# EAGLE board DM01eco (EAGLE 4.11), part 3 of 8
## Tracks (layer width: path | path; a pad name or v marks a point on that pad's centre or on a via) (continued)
CYC_SEL4  (via drill 0.61) (continued)
  Top 0.152: v159.38,17.78 v146.69,5.08
  Route2 0.152: v116.84,3.81 128.27,3.81 128.91,4.45 146.05,4.45 v146.69,5.08 | v159.38,17.78 175.26,33.66 181.61,33.66 187.96,40.01 194.31,40.01 200.66,46.35 207.01,46.35 215.9,55.24 215.9,56.52 v219.07,59.69 | v215.9,67.31 215.9,67.95 241.3,93.34 241.3,94.62 241.94,95.25 241.94,97.16 242.57,97.79 C13.R2
  Route15 0.152: v116.84,3.81 113.67,6.99 107.95,6.99 104.14,10.79 97.79,10.79 91.44,17.14 86.36,17.14 69.85,33.66 63.5,33.66 60.33,36.83 53.98,36.83 40.01,50.8 34.29,45.09 30.48,45.09 D30.K2
  Bottom 0.152: v219.07,59.69 219.07,62.87 215.9,66.04 v215.9,67.31
CYC_SEL5  (via drill 0.61)
  Top 0.152: v121.92,278.13 105.41,278.13 81.92,254.64 81.92,252.09 81.28,251.46 A26.K2
  Route2 0.152: v230.5,114.94 231.14,114.94 233.04,116.84 233.04,118.11 234.95,120.02 234.95,123.19 230.5,127.64 231.78,128.91 231.78,134.62 v234.31,137.16 | v214,165.1 210.82,168.28 213.36,170.81 213.36,172.09 211.46,173.99 212.09,174.62 212.09,175.9 219.07,182.88 v219.07,193.68
  Route15 0.152: v219.07,193.68 219.07,198.12 209.55,207.65 208.28,207.65 196.85,219.08 191.77,219.08 167,243.84 166.37,243.84 165.1,245.11 165.1,246.38 149.22,262.25 142.24,262.25 126.36,278.13 v121.92,278.13
  Bottom 0.152: v230.5,114.94 233.68,111.76 233.68,109.86 235.59,107.95 234.31,106.68 234.31,104.14 238.76,99.7 238.76,99.06 241.94,95.89 241.94,94.62 242.57,93.98 242.57,92.71 C13.T2 | v234.31,137.16 236.22,139.06 235.59,139.7 235.59,143.51 v214,165.1
CYC_SEL6  (via drill 0.61)
  Top 0.152: v130.81,75.57 132.72,75.57 141.6,84.46 142.24,84.46 144.15,86.36 v144.15,87 | v167,69.22 v177.8,80.01 | v188.59,71.75 195.58,71.75 200.03,76.2 200.03,78.11 211.46,89.54 212.09,89.54 213.36,90.81 v219.07,90.81 | v234.31,76.84 242.57,85.09 C13.V2
  Route2 0.152: v14.61,215.9 15.88,217.17 15.88,245.11 17.14,246.38 17.14,250.19 A31.K2
  Route15 0.152: v14.61,215.9 14.61,205.11 15.88,203.84 15.88,192.41 57.78,150.5 60.96,150.5 88.27,123.19 v88.9,123.19 | v99.69,111.12 97.16,108.59 98.42,107.32 98.42,106.68 111.76,93.34 116.84,93.34 117.47,92.71 117.47,90.17 116.2,88.9 120.02,85.09 120.02,84.46 127.64,76.84 129.54,76.84 v130.81,75.57
  Bottom 0.152: v88.9,123.19 88.9,121.92 v99.69,111.12 | v144.15,87 144.15,86.36 154.31,76.2 155.57,76.2 158.75,73.03 163.19,73.03 v167,69.22 | v177.8,80.01 180.34,80.01 v188.59,71.75 | v219.07,90.81 219.07,88.27 222.25,85.09 222.25,84.46 224.79,81.92 229.24,81.92 v234.31,76.84
DA0  (via drill 0.61)
  Top 0.152: v322.58,201.93 321.94,201.93 319.4,199.39 319.4,197.49 B07.D2 | v317.5,213.36 317.5,217.17 v341.63,241.3
  Bottom 0.152: v322.58,201.93 322.58,204.47 324.49,206.38 v317.5,213.36 | v341.63,241.3 320.68,262.25 320.68,264.8 319.4,266.06 A07.D2
DA0-0  (via drill 0.61)
  Top 0.152: v347.35,87 343.54,87 342.9,86.36 342.9,85.73 334.64,77.47 333.38,77.47 320.04,64.14 320.04,62.87 319.4,62.23 319.4,60.96 D07.D2 | v354.33,83.82 358.14,83.82 394.33,120.02 394.33,122.56 394.97,123.19 C01.F2
  Bottom 0.152: v347.35,87 347.35,86.36 349.88,83.82 v354.33,83.82
DA0-1  (via drill 0.61)
  Top 0.152: v303.53,40.01 308.61,40.01 314.96,46.35 320.04,46.35 323.85,50.16 325.12,50.16 327.66,52.7 333.38,52.7 353.06,72.39 353.06,73.66 361.95,82.55 363.22,82.55 394.33,113.67 394.33,116.21 394.97,116.84 C01.J2
  Route15 0.152: v303.53,40.01 303.53,40.64 300.99,43.18 295.91,43.18 294,45.09 288.29,39.37 286.38,39.37 285.75,40.01 280.04,40.01 278.13,41.91 277.5,41.91 276.23,43.18 269.88,43.18 255.91,57.15 255.91,59.69 D12.D2
DA0-2  (via drill 0.61)
  Top 0.152: v247.01,15.88 v237.49,6.35 | v270.51,1.27 353.06,1.27 374.65,22.86 374.65,23.5 v393.7,42.55 | v377.19,73.03 377.19,74.3 v385.44,82.55
  Route2 0.152: v192.41,55.88 192.41,59.69 D17.D2 | v385.44,82.55 389.25,82.55 393.7,87 393.7,88.27 396.88,91.44 396.88,96.52 403.23,102.87 403.23,104.14 403.86,104.78 403.86,105.41 401.95,107.32 v401.32,106.68
  Route15 0.152: v393.7,42.55 395.61,44.45 389.89,50.16 389.89,51.43 392.43,53.98 377.19,69.22 v377.19,73.03
  Bottom 0.152: v192.41,55.88 193.04,55.88 203.84,45.09 203.84,43.18 202.56,41.91 203.2,41.27 203.2,40.01 207.65,35.56 207.65,34.92 211.46,31.12 212.09,31.12 236.85,6.35 v237.49,6.35 | v247.01,15.88 247.01,15.24 248.28,13.97 253.37,13.97 261.62,5.71 266.06,5.71 v270.51,1.27 | v401.32,106.68 401.32,107.32 399.42,109.22 396.88,109.22 395.61,110.49 C01.L2
DA0-3  (via drill 0.61)
  Top 0.152: v163.19,52.7 163.19,53.98 168.28,59.05 168.28,64.14 168.91,64.77 173.99,64.77 182.88,73.66 v183.51,73.66 | v201.29,73.03 214,73.03 215.9,74.93 217.17,74.93 v225.43,83.19
  Route2 0.152: v146.69,71.12 144.78,73.03 141.6,73.03 140.34,71.75 137.16,71.75 128.91,63.5 128.91,60.96 D22.D2 | v331.47,6.99 332.74,6.99 378.46,52.7 384.18,52.7 400.05,68.58 400.05,73.03 403.23,76.2 403.23,78.74 v403.86,79.38
  Route15 0.152: v183.51,73.66 183.51,74.3 187.96,78.74 193.68,73.03 v201.29,73.03 | v225.43,83.19 229.24,83.19 276.23,36.2 285.75,36.2 294,44.45 v331.47,6.99 | v403.86,79.38 403.86,83.82 405.13,85.09 400.05,90.17 400.05,91.44 399.42,92.08 399.42,93.98 401.32,95.89 396.88,100.33 396.88,102.87 395.61,104.14 C01.N2
  Bottom 0.152: v146.69,71.12 146.69,70.48 162.56,54.61 162.56,53.34 v163.19,52.7
DA0-4  (via drill 0.61)
  Top 0.152: v92.71,35.56 93.98,35.56 120.65,62.23 121.28,62.23 v123.19,64.14 | v157.48,40.01 159.38,38.1 160.66,39.37 161.29,39.37 178.44,56.52 178.44,59.05 177.16,60.32 179.07,62.23 v179.71,62.23 | v201.93,41.27 202.56,41.27 203.84,42.55 209.55,42.55 219.07,52.07 224.79,52.07 227.33,54.61 v227.33,55.24
  Route2 0.152: v335.28,12.07 337.19,12.07 381.63,56.52 381.63,59.05 380.37,60.32 381.63,61.59 386.08,61.59 387.35,62.87 387.35,65.41 386.08,66.67 393.06,73.66 393.7,73.66 394.97,74.93 387.99,81.92 386.08,81.92 385.44,81.28 383.54,83.19 384.81,84.46 384.81,85.73 389.25,90.17 389.89,90.17 394.33,94.62 394.33,97.16 394.97,97.79 C01.R2
  Bottom 0.152: v92.71,35.56 68.58,59.69 65.41,59.69 D27.D2 | v123.19,64.14 125.73,66.67 139.06,53.34 139.7,53.34 140.34,52.7 145.41,52.7 157.48,40.64 v157.48,40.01 | v179.71,62.23 182.88,59.05 184.15,59.05 v201.93,41.27 | v227.33,55.24 227.33,54.61 232.41,49.53 237.49,49.53 269.88,17.14 269.88,15.24 275.59,9.53 283.85,9.53 286.38,6.99 330.2,6.99 v335.28,12.07
DA0-5  (via drill 0.61)
  Top 0.152: v241.94,38.1 244.47,40.64 v244.47,44.45 | v216.53,76.84 v216.53,80.01 | v98.42,230.5 97.16,231.78 121.28,255.91 v121.92,255.91
  Route2 0.152: v401.95,68.58 400.69,68.58 384.18,52.07 384.18,46.35 v349.25,11.43
  Route15 0.152: v201.29,99.7 200.03,99.7 196.85,102.87 196.85,104.14 188.59,112.4 187.96,112.4 180.97,119.38 180.97,125.73 161.29,145.41 161.29,147.32 157.48,151.13 157.48,152.4 142.88,167 142.88,172.72 135.89,179.71 130.18,179.71 117.47,192.41 117.47,197.49 116.84,198.12 116.84,200.03 112.39,204.47 111.76,204.47 107.95,208.28 107.95,209.55 104.78,212.72 104.78,224.16 v98.42,230.5
  Bottom 0.152: v401.95,68.58 401.32,69.22 405.13,73.03 405.13,79.38 395.61,88.9 395.61,91.44 C01.T2 | v349.25,11.43 337.19,11.43 327.66,1.91 274.32,1.91 268.61,7.62 260.99,7.62 250.19,18.41 250.19,20.32 252.09,22.23 245.75,28.58 245.75,29.84 241.3,34.29 241.3,37.47 v241.94,38.1 | v244.47,44.45 244.47,48.89 v216.53,76.84 | v216.53,80.01 216.53,81.92 213.36,85.09 213.36,87 202.56,97.79 202.56,98.43 v201.29,99.7 | v121.92,255.91 121.92,257.81 117.47,262.25 117.47,264.8 116.2,266.06 A23.D2
DA0-6  (via drill 0.61)
  Top 0.152: v69.22,13.34 97.16,13.34 104.78,20.95 104.78,21.59 v108.58,25.4 | v159.38,1.91 159.38,5.08 180.34,26.04 180.97,26.04 v182.25,27.3 | v210.82,1.91 214.63,1.91 228.6,15.88 228.6,16.51 232.41,20.32 v234.95,20.32 | v250.19,5.08 265.43,5.08 267.97,7.62 269.24,7.62 v313.69,52.07
  Route2 0.152: v87.63,229.87 87.63,228.6 81.92,222.89 81.92,217.81 74.93,210.82 74.93,209.55 18.41,153.03 18.41,142.88 15.88,140.34 15.88,128.27 3.17,115.57 3.17,67.95 63.5,7.62 v69.22,13.34 | v360.68,17.14 361.31,17.14 396.88,52.7 396.88,58.42 403.23,64.77 403.23,66.04 403.86,66.67 403.86,67.95 401.32,70.48 403.23,72.39 403.23,75.57 403.86,76.2 403.86,78.11 405.13,79.38 396.88,87.63 395.61,86.36 C01.V2
  Route15 0.152: v87.63,229.87 86.36,229.87 66.67,249.56 66.67,255.27 55.88,266.06 52.7,266.06 A28.D2 | v108.58,25.4 109.86,25.4 117.47,17.78 123.19,17.78 132.08,8.89 152.4,8.89 v159.38,1.91 | v182.25,27.3 184.15,27.3 197.49,13.97 198.75,13.97 v210.82,1.91
  Bottom 0.152: v250.19,5.08 v234.95,20.32 | v313.69,52.07 313.69,50.16 346.07,17.78 352.43,17.78 353.06,17.14 v360.68,17.14
DA1  (via drill 0.61)
  Route2 0.152: v313.69,199.39 313.69,200.66 324.49,211.46 324.49,212.72 333.38,221.62 v333.38,225.43
  Route15 0.152: v333.38,225.43 333.38,229.87 323.85,239.4 323.85,240.66 320.68,243.84 320.68,261.62 321.94,262.89 A07.E2
  Bottom 0.152: v313.69,199.39 318.77,194.31 318.77,191.14 B07.F2
DA1-0  (via drill 0.61)
  Top 0.152: v318.77,62.87 318.77,63.5 340.36,85.09 340.36,85.73 341.63,87 342.26,87 353.06,97.79 353.06,98.43 354.33,99.7 354.96,99.7 362.58,107.32 363.22,107.32 378.46,122.56 381.63,122.56 382.27,123.19 C02.F2
  Bottom 0.152: v318.77,62.87 321.94,59.69 321.94,57.78 D07.E2
DA1-1  (via drill 0.61)
  Top 0.152: v285.75,80.65 285.12,80.65 262.25,57.78 259.08,57.78 D12.E2 | v325.75,62.23 325.75,63.5 330.2,67.95 332.11,67.95 333.38,69.22 333.38,70.48 346.07,83.19 351.15,83.19 365.76,97.79 365.76,98.43 367.03,99.7 367.67,99.7 381.63,113.67 381.63,116.21 382.27,116.84 C02.J2
  Bottom 0.152: v285.75,80.65 287.65,80.65 295.27,73.03 300.99,73.03 303.53,75.57 307.98,71.12 311.79,71.12 314.96,67.95 320.04,67.95 v325.75,62.23
DA1-2  (via drill 0.61)
  Top 0.152: v285.12,9.53 309.88,9.53 340.36,40.01 345.44,40.01 351.15,45.72 351.79,45.72 391.16,85.09 391.16,87 389.25,88.9 392.43,92.08 v393.06,92.08
  Route15 0.152: v285.12,9.53 280.67,13.97 260.99,13.97 257.81,17.14 251.46,17.14 249.56,19.05 248.28,19.05 247.01,20.32 247.01,20.95 231.78,36.2 226.06,36.2 219.71,42.55 213.36,42.55 199.39,56.52 195.58,56.52 D17.E2
  Bottom 0.152: v393.06,92.08 392.43,92.08 389.89,94.62 389.89,96.52 391.8,98.43 387.35,102.87 386.71,102.87 384.18,105.41 384.18,109.22 382.9,110.49 C02.L2
DA1-3  (via drill 0.61)
  Top 0.152: v154.31,77.47 153.67,77.47 147.96,71.75 147.96,70.48 135.25,57.78 132.08,57.78 D22.E2 | v184.15,63.5 186.06,63.5 193.68,71.12 197.49,71.12 v210.19,83.82 | v296.55,13.97 307.34,13.97 v318.13,24.77 | v364.49,73.03 365.12,73.03 368.3,76.2 368.3,78.74 370.84,81.28 370.84,83.19 v386.71,99.06
  Route2 0.152: v318.13,24.77 361.95,68.58 361.95,70.48 v364.49,73.03
  Route15 0.152: v154.31,77.47 158.75,73.03 170.18,73.03 177.8,65.41 182.25,65.41 182.88,64.77 183.51,64.77 184.15,64.14 v184.15,63.5
  Bottom 0.152: v210.19,83.82 211.46,83.82 219.07,76.2 219.07,74.93 251.46,42.55 256.54,42.55 257.18,41.91 257.18,37.47 260.35,34.29 260.35,33.66 276.86,17.14 283.21,17.14 286.38,13.97 v296.55,13.97 | v386.71,99.06 386.08,99.06 384.18,100.97 384.18,102.87 382.9,104.14 C02.N2
DA1-4  (via drill 0.61)
  Top 0.152: v108.58,90.17 107.95,89.54 107.95,88.27 102.87,83.19 92.08,83.19 85.09,76.2 85.09,74.93 81.28,71.12 79.38,71.12 68.58,60.32 68.58,57.78 D27.E2 | v134.62,64.77 136.53,64.77 142.88,71.12 145.41,71.12 146.69,72.39 147.96,72.39 154.31,78.74 154.31,80.65 v158.12,84.46 | v265.43,33.66 265.43,34.29 270.51,39.37 275.59,39.37 293.37,57.15 294.64,57.15 295.91,58.42 301.62,58.42 317.5,74.3 318.77,74.3 v321.94,77.47 | v335.28,65.41 337.82,62.87 340.36,65.41 345.44,65.41 352.43,72.39 352.43,74.93 v361.95,84.46 | v375.92,74.93 375.92,75.57 v388.62,88.27
  Route2 0.152: v169.54,74.93 177.8,74.93 187.96,85.09 189.23,85.09 191.13,87 v194.31,87
  Route15 0.152: v194.31,87 197.49,83.82 198.75,83.82 209.55,73.03 214.63,73.03 231.14,56.52 231.78,56.52 233.04,55.24 233.04,53.34 234.31,52.07 235.59,52.07 254,33.66 260.35,33.66 260.99,33.02 263.52,33.02 264.8,34.29 v265.43,33.66
  Bottom 0.152: v108.58,90.17 111.76,87 116.84,87 117.47,86.36 117.47,81.92 133.35,66.04 133.35,65.41 133.99,64.77 v134.62,64.77 | v158.12,84.46 158.75,84.46 159.38,83.82 160.66,83.82 v169.54,74.93 | v321.94,77.47 323.85,77.47 330.83,70.48 330.83,69.22 332.11,67.95 332.74,67.95 v335.28,65.41 | v361.95,84.46 362.58,83.82 368.3,83.82 368.94,83.19 369.57,83.19 370.84,81.92 370.84,80.01 v375.92,74.93 | v388.62,88.27 388.62,89.54 386.71,91.44 386.71,92.71 385.44,93.98 384.81,93.98 384.18,94.62 384.18,96.52 382.9,97.79 C02.R2
DA1-5  (via drill 0.61)
  Top 0.152: v381,48.26 379.73,46.99 378.46,46.99 351.79,20.32 346.71,20.32 331.47,5.08 305.44,5.08 304.8,4.45 290.83,4.45 v287.02,8.26
  Route2 0.152: v371.48,76.2 381,85.73 381,86.36 382.27,87.63 382.27,91.44 C02.T2 | v231.78,15.88 231.78,17.14 229.87,19.05 222.88,12.07 220.34,12.07 218.44,13.97 217.17,12.7 212.72,12.7 208.91,8.89 194.31,8.89 193.68,8.26 158.12,8.26 155.57,5.71 154.31,5.71 153.67,5.08 151.76,5.08 151.13,4.45 147.32,4.45 146.69,3.81 139.7,3.81 v139.06,3.18 | v5.08,123.19 1.27,127 13.34,139.06 13.34,148.59 66.67,201.93 66.67,211.46 69.85,214.63 69.85,217.17 114.3,261.62 117.47,261.62 118.75,262.89 A23.E2
  Route15 0.152: v371.48,76.2 371.48,74.3 387.35,58.42 387.35,54.61 v381,48.26 | v287.02,8.26 259.08,8.26 255.27,12.07 235.59,12.07 v231.78,15.88 | v104.14,30.48 97.79,36.83 91.44,36.83 v5.08,123.19
  Bottom 0.152: v139.06,3.18 132.72,3.18 121.92,13.97 121.28,13.97 107.31,27.94 106.68,27.94 v104.14,30.48
DA1-6  (via drill 0.61)
  Top 0.152: v130.18,285.75 125.73,281.3 99.69,281.3 97.79,279.4 85.09,279.4 83.82,278.13 73.66,278.13 67.31,271.78 60.96,271.78 55.88,266.7 55.88,264.16 A28.E2 | v244.47,187.33 243.84,187.33 241.3,184.78 241.3,181.61 242.57,180.34 v240.66,178.44 | v340.36,76.2 340.36,76.84 346.07,82.55 351.79,82.55 356.24,87 v360.05,87
  Route2 0.152: v360.05,87 360.05,85.09 362.58,82.55 365.12,82.55 370.84,76.84 370.2,76.2 371.48,74.93 382.27,85.73 C02.V2
  Route15 0.152: v130.18,285.75 132.72,288.29 136.53,288.29 149.22,275.59 149.22,274.95 152.4,271.78 158.12,271.78 200.03,229.87 205.74,229.87 211.46,224.16 212.72,224.16 213.36,223.52 218.44,223.52 232.41,209.55 233.04,209.55 234.95,207.65 234.95,203.84 233.68,202.56 241.94,194.31 241.94,191.77 240.66,190.5 243.84,187.33 v244.47,187.33 | v240.66,178.44 240.66,177.16 260.35,157.48 260.35,156.84 264.16,153.03 264.16,150.5 283.21,131.44 283.21,130.81 327.66,86.36 327.66,85.73 330.83,82.55 334.01,82.55 v340.36,76.2
DA2  (via drill 0.61)
  Top 0.152: v323.85,186.69 321.94,184.78 319.4,184.78 B07.J2 | v318.77,207.65 318.77,212.09 v341.63,234.95
  Route15 0.152: v323.85,186.69 323.85,187.96 318.77,193.04 322.58,196.85 324.49,194.94 327.02,194.94 328.93,196.85 318.77,207.01 v318.77,207.65
  Bottom 0.152: v341.63,234.95 323.21,253.37 323.21,255.91 322.58,256.54 A07.H2
DA2-0  (via drill 0.61)
  Top 0.152: v342.26,73.66 322.58,53.98 322.58,51.43 D07.H2 | v339.09,78.74 340.36,78.74 353.06,91.44 353.06,92.08 354.33,93.34 355.6,93.34 v375.92,113.67
  Bottom 0.152: v342.26,73.66 342.26,75.57 v339.09,78.74 | v375.92,113.67 375.92,114.3 370.84,119.38 370.84,122.56 370.2,123.19 C03.F2
DA2-1  (via drill 0.61)
  Top 0.152: v271.14,55.24 266.7,55.24 262.89,51.43 259.08,51.43 D12.H2
  Route2 0.152: v309.25,22.86 309.88,22.86 343.54,56.52 343.54,59.05 342.26,60.32 343.54,61.59 343.54,62.87 349.88,69.22 349.88,73.03 353.06,76.2 353.06,79.38 358.77,85.09 v358.77,88.27 | v355.6,98.43 355.6,99.7 359.41,103.51 359.41,104.14 368.94,113.67 368.94,116.21 369.57,116.84 C03.J2
  Bottom 0.152: v271.14,55.24 271.14,54.61 279.4,46.35 285.75,46.35 v309.25,22.86 | v358.77,88.27 358.77,93.34 355.6,96.52 v355.6,98.43
DA2-2  (via drill 0.61)
  Top 0.152: v259.08,20.95 260.99,19.05 262.25,20.32 262.89,20.32 284.48,41.91 284.48,42.55 285.75,43.81 287.02,43.81 295.27,52.07 298.45,52.07 302.89,47.62 307.34,52.07 307.98,52.07 314.96,59.05 320.04,59.05 320.68,59.69 320.68,64.14 321.31,64.77 326.39,64.77 330.83,69.22 330.83,73.66 v333.38,76.2
  Route2 0.152: v203.2,55.24 199.39,51.43 195.58,51.43 D17.H2 | v333.38,76.2 342.9,85.73 342.9,87 353.06,97.16 354.96,97.16 356.87,95.25 368.94,107.32 368.94,109.86 369.57,110.49 C03.L2
  Route15 0.152: v203.2,55.24 207.01,55.24 213.36,48.89 219.71,48.89 238.76,29.84 244.47,29.84 250.82,23.5 256.54,23.5 v259.08,20.95
DA2-3  (via drill 0.61)
  Top 0.152: v172.72,83.82 160.66,71.75 154.94,71.75 153.67,70.48 153.67,69.85 148.59,64.77 143.51,64.77 139.06,60.32 140.34,59.05 140.34,56.52 135.25,51.43 132.08,51.43 D22.H2 | v217.81,73.03 217.81,73.66 227.33,83.19 227.33,85.73 238.76,97.16 243.84,97.16 244.47,97.79 v244.47,98.43 | v373.38,109.86 375.29,107.95 374.01,106.68 371.48,106.68 370.2,105.41 C03.N2
  Route2 0.152: v190.5,66.04 192.41,64.14 193.04,64.77 200.03,64.77 203.2,67.95 209.55,67.95 213.36,71.75 216.53,71.75 v217.81,73.03 | v269.88,67.31 271.14,67.31 276.23,72.39 278.76,72.39 290.83,84.46 290.83,85.73 296.55,91.44 296.55,92.08 307.98,103.51 307.98,109.22 320.68,121.92 327.02,121.92 327.66,122.56 334.01,122.56 341.63,130.18 v342.26,130.18
  Route15 0.152: v244.47,98.43 245.11,98.43 247.65,95.89 247.65,93.34 243.21,88.9 264.16,67.95 269.24,67.95 v269.88,67.31
  Bottom 0.152: v172.72,83.82 172.72,83.19 189.87,66.04 v190.5,66.04 | v342.26,130.18 343.54,128.91 349.25,128.91 353.06,125.09 358.14,125.09 358.77,124.46 358.77,120.02 359.41,119.38 364.49,119.38 365.76,118.11 365.76,117.48 367.03,116.21 368.94,116.21 372.75,112.4 372.75,110.49 v373.38,109.86
DA2-4  (via drill 0.61)
  Top 0.152: v230.5,3.81 233.04,1.27 242.57,1.27 244.47,3.18 262.25,3.18 263.52,4.45 265.43,4.45 266.06,5.08 270.51,5.08 271.14,5.71 273.69,5.71 296.55,28.58 v296.55,29.21 | v357.5,88.27 357.5,88.9 365.76,97.16 368.94,97.16 369.57,97.79 C03.R2
  Route2 0.152: v142.88,2.54 144.15,2.54 144.78,3.18 156.21,3.18 156.84,3.81 161.93,3.81 163.19,5.08 177.8,5.08 179.71,6.99 188.59,6.99 189.23,7.62 214.63,7.62 v219.07,12.07 | v296.55,29.21 303.53,22.23 342.9,61.59 342.9,62.87 349.25,69.22 349.25,73.03 352.43,76.2 352.43,83.19 v357.5,88.27
  Route15 0.152: v142.88,2.54 140.34,5.08 132.08,5.08 130.81,6.35 125.73,6.35 125.09,6.99 120.65,6.99 113.67,13.97 108.58,13.97 93.34,29.21 92.08,29.21 90.81,30.48 90.81,31.12 71.75,50.16 68.58,50.16 D27.H2
  Bottom 0.152: v219.07,12.07 222.25,12.07 v230.5,3.81
DA2-5  (via drill 0.61)
  Top 0.152: v123.19,257.18 123.19,257.81 146.69,281.3 169.54,281.3 176.53,288.29 202.56,288.29 203.2,287.65 203.84,288.29 207.65,288.29 208.28,288.92 214,288.92 v215.9,290.83 | v375.92,96.52 375.92,95.89 372.11,92.08 370.2,92.08 C03.T2
  Route2 0.152: v215.9,290.83 215.9,290.19 217.17,288.92 248.92,288.92 250.82,290.83 260.99,290.83 262.25,289.56 v263.52,290.83 | v368.3,196.85 368.3,195.58 372.75,191.14 370.84,189.23 370.84,185.42 372.11,184.15 369.57,181.61 369.57,180.34 368.3,179.07 368.3,175.9 372.11,172.09 371.48,171.45 371.48,170.18 351.79,150.5 346.71,150.5 v342.9,146.69
  Route15 0.152: v123.19,257.18 119.38,257.18 A23.H2 | v329.56,255.27 325.12,250.83 333.38,242.57 333.38,236.22 368.94,200.66 368.94,198.75 367.67,197.49 v368.3,196.85 | v342.9,146.69 342.9,143.51 344.17,142.24 344.17,139.7 358.77,125.09 358.77,119.38 363.22,114.94 363.22,114.3 360.68,111.76 v361.31,111.12
  Bottom 0.152: v263.52,290.83 266.06,290.83 269.88,287.02 271.14,288.29 280.67,288.29 282.57,286.38 289.56,286.38 290.19,285.75 293.37,285.75 295.27,283.84 304.8,283.84 330.83,257.81 330.83,256.54 v329.56,255.27 | v361.31,111.12 361.31,110.49 362.58,109.22 364.49,109.22 366.39,111.12 371.48,106.05 371.48,100.33 375.29,96.52 v375.92,96.52
DA2-6  (via drill 0.61)
  Top 0.152: v237.49,217.81 237.49,214.63 228.6,205.74 228.6,205.11 219.07,195.58 217.81,195.58 v217.17,194.94
  Route2 0.152: v123.83,290.83 120.02,290.83 118.75,289.56 111.12,289.56 102.87,281.3 99.69,281.3 97.16,278.76 85.09,278.76 83.82,277.5 79.38,277.5 59.69,257.81 55.88,257.81 A28.H2 | v245.75,149.86 249.56,149.86 v250.82,151.13 | v285.75,127 287.65,127 294,120.65 302.26,128.91 310.51,128.91 311.79,127.64 v312.42,128.27
  Route15 0.152: v142.24,286.38 154.31,286.38 158.75,281.94 173.35,281.94 201.93,253.37 v201.93,252.73 | v219.07,235.59 224.16,230.5 224.79,230.5 v237.49,217.81 | v217.17,194.94 217.17,194.31 219.07,192.41 222.25,192.41 223.52,193.68 234.31,182.88 234.31,182.25 234.95,181.61 234.95,179.71 233.04,177.8 231.14,179.71 228.6,179.71 227.33,178.44 226.69,179.07 225.43,179.07 224.79,179.71 222.25,179.71 220.34,177.8 229.24,168.91 229.24,166.37 227.97,165.1 232.41,160.66 237.49,160.66 245.75,152.4 v245.75,149.86 | v312.42,128.27 312.42,127.64 314.96,125.09 321.31,125.09 340.36,106.05 348.62,106.05 350.52,107.95 354.96,103.51 356.24,103.51 v356.87,102.87
  Bottom 0.152: v123.83,290.83 137.79,290.83 v142.24,286.38 | v201.93,252.73 202.56,252.73 216.53,238.76 216.53,238.12 v219.07,235.59 | v250.82,151.13 254,151.13 254.63,150.5 257.18,150.5 271.14,136.53 271.14,135.89 272.42,134.62 275.59,134.62 277.5,136.53 281.94,132.08 281.94,131.44 285.75,127.64 v285.75,127 | v356.87,102.87 356.87,102.23 368.3,90.81 368.3,89.54 368.94,88.9 368.94,87 369.57,86.36 C03.V2
DA3  (via drill 0.61)
  Top 0.152: v313.69,238.12 313.69,239.4 320.68,246.38 320.68,248.92 321.94,250.19 A07.K2
  Route2 0.152: v325.12,173.36 325.12,173.99 339.73,188.59 339.73,189.23 349.25,198.75 v349.25,201.93
  Bottom 0.152: v325.12,173.36 325.12,173.99 321.94,177.16 319.4,177.16 B07.L2 | v349.25,201.93 348.62,201.93 318.77,231.78 318.77,232.41 313.69,237.49 v313.69,238.12
DA3-0  (via drill 0.61)
  Top 0.152: v313.06,62.23 313.06,64.14 340.36,91.44 340.36,92.08 341.63,93.34 342.26,93.34 361.95,113.03 v361.95,114.94
  Bottom 0.152: v313.06,62.23 313.69,62.23 320.68,55.24 320.68,50.16 321.94,48.89 321.94,45.09 D07.K2 | v361.95,114.94 361.95,116.21 358.14,120.02 358.14,122.56 357.5,123.19 C04.F2
DA3-1  (via drill 0.61)
  Top 0.152: v298.45,69.85 298.45,70.48 309.88,81.92 311.15,81.92 311.79,82.55 318.77,82.55 332.74,96.52 333.38,96.52 353.06,116.21 356.24,116.21 356.87,116.84 C04.J2
  Route2 0.152: v266.7,41.27 266.7,41.91 270.51,45.72 275.59,45.72 298.45,68.58 v298.45,69.85
  Bottom 0.152: v266.7,41.27 265.43,42.55 264.16,42.55 263.52,43.18 260.35,43.18 259.71,43.81 259.08,43.81 D12.K2
DA3-2  (via drill 0.61)
  Top 0.152: v247.65,1.27 253.37,1.27 254.63,2.54 262.25,2.54 263.52,3.81 265.43,3.81 266.06,4.45 270.51,4.45 271.14,5.08 273.69,5.08 v307.34,38.73 | v346.71,99.7 344.81,101.6 353.06,109.86 356.24,109.86 356.87,110.49 C04.L2
  Route2 0.152: v310.51,47.62 306.7,51.43 317.5,62.23 317.5,62.87 320.68,66.04 320.68,70.48 336.55,86.36 336.55,87 340.36,90.81 345.44,90.81 346.07,91.44 346.07,95.89 347.98,97.79 v348.62,97.79
  Route15 0.152: v218.44,30.48 217.17,31.75 217.17,33.02 215.9,34.29 215.26,34.29 207.01,42.55 200.66,42.55 199.39,43.81 195.58,43.81 D17.K2 | v348.62,97.79 v346.71,99.7
  Bottom 0.152: v247.65,1.27 v218.44,30.48 | v307.34,38.73 313.06,44.45 310.51,46.99 v310.51,47.62
DA3-3  (via drill 0.61)
  Top 0.152: v268.61,20.32 269.88,20.32 v299.08,49.53
  Route2 0.152: v154.94,70.48 154.31,70.48 148.59,64.77 142.88,64.77 128.91,50.8 131.44,48.26 131.44,45.09 D22.K2 | v193.68,31.12 193.68,32.38 196.85,35.56 196.85,36.2 200.66,40.01 208.28,40.01 211.46,36.83 212.09,36.83 214.63,34.29 216.53,36.2 221.62,36.2 236.85,51.43 v236.85,52.07 | v299.08,49.53 335.92,86.36 335.92,87 340.36,91.44 340.36,92.08 341.63,93.34 342.9,93.34 353.06,103.51 356.24,103.51 356.87,104.14 C04.N2
  Route15 0.152: v154.94,70.48 154.31,69.85 159.38,64.77 160.02,64.77 161.93,62.87 161.93,62.23 165.1,59.05 165.74,59.05 171.45,53.34 171.45,52.7 193.04,31.12 v193.68,31.12
  Bottom 0.152: v236.85,52.07 236.85,50.8 266.7,20.95 267.97,20.95 v268.61,20.32
DA3-4  (via drill 0.61)
  Top 0.152: v127,7.62 135.89,7.62 178.44,50.16 v178.44,50.8 | v351.15,72.39 351.15,74.93 352.43,76.2 352.43,77.47 365.76,90.81 v366.39,90.81
  Route2 0.152: v106.05,21.59 100.33,15.88 72.39,43.81 68.58,43.81 D27.K2 | v267.97,2.54 277.5,2.54 278.76,3.81 290.83,3.81 308.61,21.59 309.25,21.59 344.17,56.52 344.17,57.78 346.07,59.69 346.07,64.77 350.52,69.22 350.52,71.75 v351.15,72.39
  Route15 0.152: v178.44,50.8 179.07,50.8 193.68,36.2 193.68,34.92 195.58,33.02 196.22,33.02 196.85,32.38 196.85,29.84 195.58,28.58 210.19,13.97 212.72,13.97 218.44,8.26 220.34,8.26 223.52,5.08 225.43,5.08 229.24,1.27 242.57,1.27 247.65,6.35 252.73,6.35 254.63,4.45 266.06,4.45 v267.97,2.54 | v366.39,90.81 366.39,91.44 365.12,92.71 365.12,93.34 361.95,96.52 358.77,96.52 357.5,97.79 C04.R2
  Bottom 0.152: v106.05,21.59 107.31,21.59 111.76,17.14 117.47,17.14 v127,7.62
DA3-5  (via drill 0.61)
  Top 0.152: v203.84,232.41 204.47,232.41 209.55,237.49 v209.55,238.12
  Route2 0.152: v152.4,274.32 147.96,269.88 146.05,271.78 136.53,271.78 119.38,254.64 119.38,251.46 A23.K2 | v259.71,184.15 259.71,182.25 260.99,180.97 258.44,178.44 258.44,177.16 244.47,163.19 244.47,156.84 240.03,152.4 240.03,150.5 250.19,140.34 253.37,143.51 257.18,143.51 267.33,153.67 269.24,153.67 v269.88,153.03
  Route15 0.152: v152.4,274.32 156.21,274.32 190.5,240.03 196.22,240.03 v203.84,232.41 | v209.55,238.12 210.19,238.12 210.82,237.49 212.09,237.49 228.6,220.98 233.04,220.98 244.47,209.55 247.65,209.55 250.19,207.01 246.38,203.2 254,195.58 254,194.31 257.18,191.14 257.18,186.69 v259.71,184.15 | v277.5,150.5 281.31,150.5 284.48,147.32 285.75,147.32 301.62,131.44 302.89,131.44 305.44,128.91 310.51,128.91 320.68,118.75 320.68,118.11 323.21,115.57 324.49,115.57 327.66,112.4 333.38,112.4 345.44,100.33 345.44,99.7 348.62,96.52 349.25,97.16 353.06,93.34 356.24,93.34 356.87,92.71 C04.T2
  Bottom 0.152: v269.88,153.03 271.14,153.03 273.69,150.5 v277.5,150.5
DA3-6  (via drill 0.61)
  Top 0.152: v21.59,224.79 21.59,226.06 55.24,259.71 57.15,257.81 57.15,256.54 55.88,255.27 55.88,251.46 A28.K2 | v141.6,71.75 145.41,71.75 152.4,78.74 v153.03,78.74 | v312.42,10.79 335.92,10.79 382.27,57.15 382.27,57.78 v384.18,59.69
  Route15 0.152: v69.85,173.99 67.31,171.45 66.04,172.72 63.5,172.72 59.05,168.28 76.2,151.13 76.2,147.32 104.78,118.75 104.78,113.67 v107.31,111.12 | v153.03,78.74 152.4,78.11 162.56,67.95 168.91,67.95 188.59,48.26 189.23,48.26 196.85,40.64 196.85,40.01 200.66,36.2 206.38,36.2 225.43,17.14 232.41,17.14 236.85,12.7 264.8,12.7 266.7,10.79 v275.59,10.79
  Bottom 0.152: v21.59,224.79 21.59,224.16 38.73,207.01 38.73,206.38 46.35,198.75 46.99,198.75 69.85,175.9 v69.85,173.99 | v107.31,111.12 107.31,109.86 111.76,105.41 111.76,104.14 109.86,102.23 111.12,100.97 111.12,100.33 115.57,95.89 115.57,94.62 117.47,92.71 117.47,87.63 121.28,83.82 127.64,83.82 128.91,82.55 130.81,82.55 v141.6,71.75 | v275.59,10.79 v312.42,10.79 | v384.18,59.69 384.18,62.23 377.19,69.22 377.19,71.75 369.57,79.38 368.94,79.38 365.12,83.19 359.41,83.19 357.5,85.09 C04.V2
DA4  (via drill 0.61)
  Top 0.152: v321.94,170.18 319.4,167.64 318.13,168.91 318.77,169.55 318.77,170.81 B07.N2
  Route2 0.152: v321.94,170.18 323.21,170.18 325.12,168.28 328.3,171.45 329.56,171.45 332.74,174.62 332.74,175.9 346.07,189.23 346.07,194.94 v353.06,201.93
  Route15 0.152: v353.06,201.93 353.69,202.56 352.43,203.84 352.43,204.47 349.25,207.65 347.98,207.65 342.9,212.72 v342.9,220.34
  Bottom 0.152: v342.9,220.34 342.9,220.98 323.21,240.66 323.21,243.21 322.58,243.84 A07.M2
DA4-0  (via drill 0.61)
  Top 0.152: v336.55,51.43 336.55,49.53 325.75,38.73 322.58,38.73 D07.M2 | v332.11,69.22 332.11,69.85 353.06,90.81 v353.69,90.81 | v349.25,95.89 347.35,97.79 354.33,104.78 v354.96,104.78
  Route15 0.152: v336.55,51.43 336.55,53.34 333.38,56.52 333.38,67.95 v332.11,69.22 | v353.69,90.81 353.69,91.44 352.43,92.71 352.43,93.34 349.88,95.89 v349.25,95.89
  Bottom 0.152: v354.96,104.78 357.5,107.32 349.88,114.94 349.25,114.94 347.98,116.21 347.98,118.11 346.07,120.02 346.07,121.92 344.81,123.19 C05.F2
DA4-1  (via drill 0.61)
  Top 0.152: v287.65,64.77 279.4,56.52 279.4,55.24 262.89,38.73 259.08,38.73 D12.M2 | v321.31,81.28 323.85,81.28 327.66,85.09 327.66,85.73 328.93,87 329.56,87 349.25,106.68 v349.25,109.86
  Route2 0.152: v287.65,64.77 288.93,64.77 295.27,71.12 299.08,71.12 309.88,81.92 311.15,81.92 311.79,82.55 320.04,82.55 v321.31,81.28
  Bottom 0.152: v349.25,109.86 349.25,110.49 346.07,113.67 346.07,115.57 344.81,116.84 C05.J2
DA4-2  (via drill 0.61)
  Top 0.152: v214.63,55.24 214.63,54.61 202.56,42.55 201.93,42.55 200.66,41.27 200.66,40.64 198.75,38.73 195.58,38.73 D17.M2 | v328.3,97.16 333.38,97.16 343.54,107.32 343.54,109.86 344.17,110.49 C05.L2
  Route2 0.152: v245.75,27.3 245.75,28.58 260.99,43.81 261.62,43.81 286.38,68.58 287.02,68.58 288.93,70.48 288.93,71.12 289.56,71.75 291.46,71.75 v292.74,73.03 | v305.44,69.85 307.34,69.85 308.61,71.12 312.42,71.12 322.58,81.28 322.58,83.19 323.21,83.82 318.77,88.27 327.66,97.16 v328.3,97.16
  Bottom 0.152: v214.63,55.24 214.63,54.61 222.25,46.99 222.25,46.35 228.6,40.01 234.95,40.01 243.21,31.75 243.21,30.48 245.75,27.94 v245.75,27.3 | v292.74,73.03 294.64,73.03 295.27,72.39 303.53,72.39 305.44,70.48 v305.44,69.85
DA4-3  (via drill 0.61)
  Top 0.152: v280.67,56.52 289.56,65.41 291.46,65.41 v292.1,66.04 | v295.27,62.87 297.18,60.96 304.17,67.95 305.44,67.95 308.61,71.12 312.42,71.12 317.5,76.2 317.5,79.38 319.4,81.28 319.4,82.55 330.2,93.34 v334.64,93.34
  Route2 0.152: v147.32,20.32 148.59,20.32 155.57,27.3 156.84,27.3 v158.12,28.58 | v202.56,1.27 207.65,1.27 209.55,3.18 210.82,3.18 212.09,1.91 212.72,2.54 221.62,2.54 222.25,3.18 227.33,3.18 255.91,31.75 255.91,32.38 257.18,33.66 258.44,33.66 260.35,35.56 260.35,36.2 v280.67,56.52 | v334.64,93.34 335.28,93.34 336.55,94.62 336.55,95.89 334.64,97.79 340.36,103.51 343.54,103.51 344.17,104.14 C05.N2
  Bottom 0.152: v147.32,20.32 146.69,20.32 133.35,33.66 133.35,34.29 132.08,35.56 132.08,37.47 D22.M2 | v158.12,28.58 158.12,27.94 172.09,13.97 177.8,13.97 186.06,5.71 188.59,5.71 189.23,5.08 192.41,5.08 194.31,3.18 200.66,3.18 v202.56,1.27 | v292.1,66.04 v295.27,62.87
DA4-4  (via drill 0.61)
  Top 0.152: v66.67,28.58 66.67,32.38 69.22,34.92 68.58,35.56 68.58,37.47 D27.M2 | v200.66,1.27 201.29,1.27 202.56,2.54 205.74,2.54 v217.17,13.97 | v304.8,5.71 331.47,5.71 v383.54,57.78
  Route2 0.152: v66.67,28.58 66.67,26.67 62.87,22.86 62.87,21.59 72.39,12.07 84.45,12.07 95.25,1.27 109.22,1.27 114.3,6.35 116.84,6.35 127.64,17.14 132.72,17.14 146.05,30.48 148.59,30.48 151.13,27.94 153.67,30.48 v154.31,30.48
  Route15 0.152: v154.31,30.48 154.94,30.48 171.45,13.97 182.88,13.97 183.51,13.34 188.59,13.34 v200.66,1.27 | v217.17,13.97 220.34,13.97 222.25,12.07 224.16,12.07 228.6,7.62 239.4,7.62 240.03,6.99 266.7,6.99 268.61,5.08 304.17,5.08 v304.8,5.71
  Bottom 0.152: v383.54,57.78 382.27,57.78 368.3,71.75 363.22,71.75 358.77,76.2 358.77,80.65 349.25,90.17 349.25,91.44 346.07,94.62 346.07,96.52 344.81,97.79 C05.R2
DA4-5  (via drill 0.61)
  Top 0.152: v112.39,229.87 113.67,229.87 117.47,233.68 117.47,238.76 118.75,240.03 118.75,243.84 A23.M2
  Route2 0.152: v231.14,113.03 231.14,114.3 232.41,115.57 238.12,115.57 238.76,116.21 247.01,116.21 252.09,111.12 253.37,112.4 260.35,112.4 264.16,116.21 270.51,116.21 276.86,122.56 283.21,122.56 286.38,125.73 288.29,125.73 296.55,117.48 302.26,123.19 303.53,123.19 v306.7,126.37
  Route15 0.152: v112.39,229.87 112.39,229.24 133.99,207.65 134.62,207.65 136.53,205.74 136.53,205.11 139.06,202.56 139.7,202.56 146.05,196.22 146.05,195.58 147.32,194.31 147.32,193.04 v147.96,192.41 | v159.38,182.25 159.38,181.61 170.81,170.18 170.81,169.55 173.35,167 173.99,167 187.96,153.03 187.96,149.86 187.32,149.22 188.59,147.96 189.87,147.96 191.13,146.69 193.68,146.69 v194.94,147.96 | v306.7,126.37 320.68,112.4 320.68,111.76 324.49,107.95 325.75,107.95 327.66,106.05 333.38,106.05 343.54,95.89 343.54,93.34 344.17,92.71 C05.T2
  Bottom 0.152: v147.96,192.41 148.59,192.41 154.31,186.69 154.31,186.06 155.57,184.78 156.84,184.78 v159.38,182.25 | v194.94,147.96 197.49,147.96 204.47,140.97 204.47,140.34 210.19,134.62 212.09,134.62 214,136.53 219.07,131.44 219.07,125.09 v231.14,113.03
DA4-6  (via drill 0.61)
  Top 0.152: v87,208.91 78.11,200.03 77.47,200.03 73.03,195.58 73.03,194.31 v71.12,192.41 | v241.3,135.89 241.3,137.16 241.94,137.8 246.38,137.8 v259.08,150.5 | v335.92,76.84 344.17,85.09 C05.V2
  Route2 0.152: v123.19,141.61 136.53,141.61 138.43,143.51 153.67,143.51 155.57,145.41 161.29,145.41 162.56,146.69 163.83,146.69 165.74,144.78 173.99,144.78 v174.62,145.41 | v201.93,122.56 206.38,122.56 219.07,135.25 219.07,140.97 227.97,149.86 229.87,149.86 238.12,141.61 240.66,141.61 243.21,139.06 241.3,137.16 v241.3,135.89 | v316.23,103.51 316.87,103.51 322.58,97.79 v321.94,97.16
  Route15 0.152: v71.12,192.41 72.39,192.41 104.78,160.02 104.78,158.75 106.05,157.48 107.31,157.48 v123.19,141.61 | v174.62,145.41 175.9,145.41 178.44,142.88 178.44,140.97 187.96,131.44 193.68,131.44 201.93,123.19 v201.93,122.56 | v286.38,134.62 293.37,127.64 294,127.64 298.45,123.19 298.45,122.56 303.53,117.48 304.17,117.48 305.44,116.21 305.44,113.67 303.53,111.76 305.44,109.86 310.51,109.86 316.23,104.14 v316.23,103.51
  Bottom 0.152: v87,208.91 78.11,217.81 79.38,219.08 79.38,223.52 59.05,243.84 55.88,243.84 A28.M2 | v259.08,150.5 270.51,150.5 v286.38,134.62 | v321.94,97.16 320.04,95.25 320.04,93.34 320.68,92.71 320.68,87.63 324.49,83.82 328.93,83.82 v335.92,76.84
DA5  (via drill 0.61)
  Top 0.152: v295.27,208.28 296.55,209.55 298.45,209.55 301.62,212.72 301.62,214.63 v314.96,227.97
  Route2 0.152: v320.68,174.62 320.68,170.81 320.04,170.18 319.4,170.18 318.13,168.91 318.77,168.28 318.77,165.74 B07.R2 | v314.96,227.97 320.68,233.68 320.68,236.22 321.94,237.49 A07.P2
  Route15 0.152: v320.68,174.62 318.77,174.62 296.55,196.85 296.55,198.12 295.27,199.39 v295.27,208.28
DA5-0  (via drill 0.61)
  Top 0.152: v363.22,69.85 325.75,32.38 322.58,32.38 D07.P2 | v323.85,109.86 322.58,111.12 v331.47,120.02
  Bottom 0.152: v363.22,69.85 342.26,90.81 341.63,90.81 339.73,92.71 339.73,93.34 337.19,95.89 336.55,95.89 330.2,102.23 330.2,102.87 329.56,103.51 328.93,103.51 327.02,105.41 327.02,106.05 323.85,109.22 v323.85,109.86 | v331.47,120.02 331.47,123.19 C06.F2
DA5-1  (via drill 0.61)
  Top 0.152: v299.72,52.07 301.62,52.07 302.26,52.7 307.98,52.7 317.5,62.23 317.5,62.87 320.68,66.04 320.68,71.12 340.36,90.81 341.63,90.81 v342.9,92.08
  Route2 0.152: v299.72,52.07 299.08,51.43 297.81,52.7 288.93,52.7 272.42,36.2 266.7,36.2 262.89,32.38 259.08,32.38 D12.P2
  Bottom 0.152: v342.9,92.08 342.9,94.62 344.17,95.89 342.26,97.79 342.26,99.7 347.35,104.78 336.55,115.57 333.38,115.57 332.11,116.84 C06.J2
DA5-2  (via drill 0.61)
  Top 0.152: v217.17,5.71 251.46,40.01 256.54,40.01 260.35,43.81 v260.35,44.45 | v290.83,74.93 292.74,74.93 296.55,71.12 302.89,77.47 302.89,79.38 314.96,91.44 314.96,92.71 313.06,94.62 314.32,95.89 314.32,96.52 324.49,106.68 327.02,106.68 328.3,105.41 328.93,106.05 329.56,106.05 330.83,107.32 330.83,109.86 331.47,110.49 C06.L2
  Route2 0.152: v260.35,44.45 261.62,44.45 285.75,68.58 285.75,69.85 v290.83,74.93
  Bottom 0.152: v217.17,5.71 217.17,6.35 195.58,27.94 195.58,31.12 D17.P2
DA5-3  (via drill 0.61)
  Top 0.152: v277.5,65.41 281.94,65.41 282.57,66.04 282.57,71.12 302.26,90.81 307.34,90.81 307.98,91.44 v307.98,95.25
  Route2 0.152: v139.7,22.23 139.7,20.95 144.78,15.88 155.57,26.67 161.93,26.67 175.26,40.01 180.97,40.01 200.03,59.05 201.29,59.05 203.84,61.59 208.28,61.59 211.46,64.77 212.72,64.77 213.36,65.41 218.44,65.41 226.69,73.66 231.78,73.66 233.04,74.93 234.31,74.93 248.92,89.54 v248.92,90.17 | v307.98,95.25 307.98,93.98 313.06,88.9 314.96,90.81 320.68,90.81 330.83,100.97 330.83,103.51 331.47,104.14 C06.N2
  Route15 0.152: v139.7,22.23 138.43,23.5 136.53,23.5 130.18,29.84 131.44,31.12 D22.P2 | v248.92,90.17 248.92,89.54 250.82,87.63 250.82,86.36 251.46,85.73 251.46,81.28 259.08,73.66 260.35,73.66 260.99,73.03 271.14,73.03 276.86,67.31 276.86,66.04 v277.5,65.41
DA5-4  (via drill 0.61)
  Route2 0.152: v194.94,59.05 193.68,57.78 193.68,53.34 193.04,52.7 187.96,52.7 181.61,46.35 180.97,46.35 166.37,31.75 161.29,36.83 153.03,36.83 151.13,34.92 149.22,36.83 146.69,36.83 143.51,33.66 137.16,33.66 136.53,33.02 130.18,33.02 104.78,7.62 99.69,7.62 94.61,2.54 68.58,28.58 68.58,31.12 D27.P2 | v241.3,39.37 243.84,39.37 257.18,52.7 257.18,59.05 260.35,62.23 260.35,63.5 261.62,64.77 262.89,64.77 v281.94,83.82 | v304.8,66.67 304.8,67.31 305.44,67.95 310.51,67.95 323.85,81.28 323.85,84.46 322.58,85.73 330.2,93.34 330.2,94.62 330.83,95.25 330.83,97.16 331.47,97.79 C06.R2
  Route15 0.152: v194.94,59.05 196.85,59.05 197.49,58.42 200.03,58.42 201.29,59.69 201.93,59.05 202.56,59.05 203.2,58.42 209.55,58.42 214.63,53.34 215.9,53.34 216.53,52.7 222.25,52.7 228.6,46.35 234.31,46.35 v241.3,39.37
  Bottom 0.152: v281.94,83.82 281.94,82.55 292.74,71.75 297.81,71.75 302.26,67.31 304.17,67.31 v304.8,66.67
DA5-5  (via drill 0.61)
  Top 0.152: v125.09,242.57 124.46,241.94 124.46,240.66 122.56,238.76 119.38,238.76 A23.P2 | v160.02,208.28 167,208.28 v179.07,220.34
  Route2 0.152: v215.9,184.78 215.26,184.78 206.38,175.9 206.38,167.64 208.28,165.74 v205.1,162.56 | v303.53,65.41 308.61,65.41 327.02,83.82 327.02,85.09 328.93,87 329.56,87 330.83,88.27 330.83,90.81 331.47,91.44 C06.T2
  Route15 0.152: v205.1,162.56 205.1,161.29 213.36,153.03 214.63,153.03 217.81,149.86 219.07,149.86 219.71,149.22 224.79,149.22 231.14,142.88 231.14,142.24 232.41,140.97 234.31,140.97 236.85,138.43 237.49,138.43 v243.21,132.72 | v287.02,81.92 287.02,80.65 296.55,71.12 298.45,71.12 303.53,66.04 v303.53,65.41
  Bottom 0.152: v125.09,242.57 125.09,241.94 137.16,229.87 137.79,229.87 146.05,221.62 146.05,220.98 146.69,220.34 147.96,220.34 v160.02,208.28 | v179.07,220.34 179.07,219.71 193.68,205.11 200.03,205.11 216.53,188.59 217.17,188.59 218.44,187.33 v215.9,184.78 | v243.21,132.72 282.57,93.34 282.57,86.36 v287.02,81.92
DA5-6  (via drill 0.61)
  Top 0.152: v69.22,227.97 71.75,225.43 88.9,242.57 v93.34,242.57 | v317.5,73.03 318.77,73.03 331.47,85.73 C06.V2
  Route2 0.152: v185.42,143.51 186.69,142.24 184.15,139.7 184.15,137.16 180.97,133.98 v180.97,130.18 | v273.05,44.45 274.95,44.45 302.26,71.75 307.34,71.75 v308.61,73.03
  Route15 0.152: v133.99,200.66 137.16,197.49 137.16,195.58 135.25,193.68 149.86,179.07 151.13,179.07 152.4,177.8 152.4,176.53 v185.42,143.51 | v223.52,87.63 224.79,87.63 228.6,83.82 229.24,83.82 251.46,61.59 257.18,61.59 267.97,50.8 267.97,50.16 273.05,45.09 v273.05,44.45
  Bottom 0.152: v69.22,227.97 59.69,237.49 55.88,237.49 A28.P2 | v93.34,242.57 93.34,241.94 114.3,220.98 119.38,220.98 133.35,207.01 133.35,203.84 132.08,202.56 v133.99,200.66 | v180.97,130.18 180.97,125.73 213.36,93.34 218.44,93.34 223.52,88.27 v223.52,87.63 | v308.61,73.03 v317.5,73.03
DA6  (via drill 0.61)
  Top 0.152: v360.05,195.58 360.05,196.22 362.58,198.75 363.22,198.75 365.12,200.66 365.12,201.3 v374.01,210.19 | v338.45,239.4 332.74,239.4 326.39,233.05 323.21,233.05 322.58,232.41 A07.S2
  Route2 0.152: v360.05,195.58 353.69,189.23 352.43,189.23 322.58,159.39 319.4,159.39 B07.T2
  Bottom 0.152: v374.01,210.19 365.12,219.08 363.86,219.08 342.9,240.03 340.36,240.03 339.09,238.76 v338.45,239.4
DA6-0  (via drill 0.61)
  Top 0.152: v320.68,34.92 320.68,39.37 344.17,62.87 v344.81,62.87 | v308.61,99.06 306.7,100.97 307.34,101.6 307.34,102.87 321.94,117.48 v321.94,118.11
  Bottom 0.152: v320.68,34.92 320.68,31.12 321.94,29.84 321.94,26.04 D07.S2 | v344.81,62.87 v308.61,99.06 | v321.94,118.11 321.94,118.75 320.68,120.02 320.68,121.92 319.4,123.19 C07.F2
DA6-1  (via drill 0.61)
  Top 0.152: v307.34,75.57 303.53,71.75 302.26,71.75 259.08,28.58 259.08,26.04 D12.S2 | v290.83,93.34 291.46,93.34 314.32,116.21 318.13,116.21 318.77,116.84 C07.J2
  Bottom 0.152: v307.34,75.57 292.1,90.81 292.1,92.08 v290.83,93.34
DA6-2  (via drill 0.61)
  Top 0.152: v205.1,20.32 206.38,20.32 245.75,59.69 245.75,60.32 254,68.58 255.27,68.58 257.81,71.12 261.62,71.12 271.14,80.65 v271.14,81.28
  Route2 0.152: v205.1,20.32 204.47,19.69 199.39,24.77 195.58,24.77 D17.S2 | v281.31,71.75 282.57,73.03 283.85,73.03 302.26,91.44 302.26,93.34 300.36,95.25 314.96,109.86 318.13,109.86 318.77,110.49 C07.L2
  Route15 0.152: v271.14,81.28 271.78,81.28 v281.31,71.75
DA6-3  (via drill 0.61)
  Top 0.152: v215.9,1.27 220.34,1.27 222.25,3.18 226.06,3.18 v234.31,11.43
  Route2 0.152: v146.05,7.62 146.69,6.99 147.32,7.62 150.5,7.62 151.13,8.26 154.94,8.26 155.57,8.89 156.84,8.89 160.02,12.07 187.32,12.07 189.87,14.61 196.85,14.61 198.12,13.34 201.29,13.34 v201.93,13.97 | v256.54,9.53 259.08,9.53 292.1,42.55 298.45,42.55 299.08,43.18 301.62,43.18 309.88,34.92 314.96,40.01 320.68,40.01 336.55,55.88 336.55,59.69 335.28,60.96 343.54,69.22 v343.54,72.39
  Route15 0.152: v234.31,11.43 254.63,11.43 v256.54,9.53
  Bottom 0.152: v146.05,7.62 132.72,20.95 127.64,20.95 126.36,22.23 128.91,24.77 131.44,24.77 D22.S2 | v201.93,13.97 201.93,12.7 212.09,2.54 213.36,2.54 214.63,1.27 v215.9,1.27 | v343.54,72.39 343.54,76.2 335.92,83.82 335.92,85.09 332.74,88.27 332.74,90.17 334.64,92.08 323.85,102.87 320.68,102.87 319.4,104.14 C07.N2
DA6-4  (via drill 0.61)
  Top 0.152: v179.07,1.27 185.42,1.27 v193.68,9.53 | v309.88,83.82 313.69,83.82 314.96,85.09 314.96,85.73 316.23,87 316.87,87 320.68,90.81 320.68,96.52 319.4,97.79 C07.R2
  Route2 0.152: v114.3,5.08 116.2,5.08 116.84,5.71 122.56,5.71 133.35,16.51 133.35,17.14 144.78,28.58 v145.41,28.58 | v193.68,9.53 208.91,9.53 216.53,17.14 222.25,17.14 226.06,20.95 231.14,20.95 234.95,24.77 234.95,27.3 233.68,28.58 251.46,46.35 256.54,46.35 262.25,52.07 262.89,52.07 264.16,53.34 264.16,55.24 262.25,57.15 264.16,59.05 269.88,59.05 280.04,69.22 280.04,71.75 281.94,73.66 283.85,73.66 299.72,89.54 v299.72,90.17
  Route15 0.152: v114.3,5.08 113.03,6.35 107.95,6.35 104.14,10.16 97.79,10.16 93.34,14.61 89.53,14.61 87.63,16.51 86.36,16.51 79.38,23.5 73.66,23.5 72.39,24.77 68.58,24.77 D27.S2
  Bottom 0.152: v145.41,28.58 145.41,27.3 170.18,2.54 170.81,2.54 171.45,1.91 178.44,1.91 v179.07,1.27 | v299.72,90.17 299.72,89.54 302.26,87 307.34,87 309.88,84.46 v309.88,83.82
DA6-5  (via drill 0.61)
  Top 0.152: v237.49,194.31 237.49,194.94 245.11,202.56 v245.75,202.56 | v210.82,238.76 210.82,238.12 193.68,220.98 192.41,220.98 v191.77,220.34 | v147.32,257.18 123.19,233.05 120.02,233.05 119.38,232.41 A23.S2
  Route15 0.152: v317.5,98.43 317.5,100.97 318.77,102.23 307.98,113.03 307.98,118.75 298.45,128.27 296.55,128.27 295.27,129.54 295.27,131.44 287.65,139.06 287.65,140.34 282.57,145.41 281.31,145.41 276.23,150.5 276.23,151.77 277.5,153.03 272.42,158.12 272.42,158.75 264.8,166.37 264.16,166.37 237.49,193.04 v237.49,194.31
  Bottom 0.152: v317.5,98.43 317.5,97.79 319.4,95.89 319.4,92.71 C07.T2 | v245.75,202.56 245.75,203.84 v210.82,238.76 | v191.77,220.34 184.78,220.34 154.31,250.83 154.31,251.46 152.4,253.37 151.13,253.37 v147.32,257.18
DA6-6  (via drill 0.61)
  Top 0.152: v239.4,46.35 239.4,46.99 254.63,62.23 255.27,62.23 260.35,67.31 260.35,67.95 264.16,71.75 267.33,71.75 277.5,81.92 285.75,81.92 v287.02,83.19
  Route2 0.152: v301.62,77.47 304.8,77.47 309.88,82.55 311.15,82.55 311.79,83.19 316.87,83.19 318.77,85.09 C07.V2
  Route15 0.152: v82.55,200.03 82.55,198.12 79.38,194.94 79.38,192.41 95.89,175.9 97.79,175.9 99.06,177.16 v99.69,176.53 | v214,67.95 222.25,59.69 222.25,59.05 231.14,50.16 231.78,50.16 232.41,49.53 237.49,49.53 238.76,48.26 238.76,46.99 v239.4,46.35
  Bottom 0.152: v82.55,200.03 82.55,201.3 76.83,207.01 76.83,208.28 66.67,218.44 66.67,223.52 59.05,231.14 55.88,231.14 A28.S2 | v99.69,176.53 100.97,176.53 124.46,153.03 124.46,149.86 140.34,133.98 140.34,131.44 138.43,129.54 149.22,118.75 156.21,118.75 162.56,112.4 168.91,112.4 177.8,103.51 178.44,103.51 184.15,97.79 184.15,97.16 187.96,93.34 193.04,93.34 196.85,89.54 196.85,87 195.58,85.73 213.36,67.95 v214,67.95 | v287.02,83.19 297.81,83.19 301.62,79.38 v301.62,77.47
DA7  (via drill 0.61)
  Top 0.152: v258.44,203.84 259.71,203.84 292.1,236.22 292.1,237.49 292.74,238.12 292.74,240.03 291.46,241.3 295.91,245.75 v300.36,245.75
  Route2 0.152: v236.22,187.33 236.85,187.33 251.46,201.93 256.54,201.93 v258.44,203.84
  Bottom 0.152: v236.22,187.33 231.78,191.77 226.06,191.77 221.62,196.22 217.81,196.22 B15.D2 | v300.36,245.75 300.99,245.75 302.89,247.65 318.13,232.41 318.13,229.87 318.77,229.24 A07.T2
DA7-0  (via drill 0.61)
  Top 0.152: v353.69,59.05 353.06,59.05 319.4,25.4 319.4,22.86 D07.T2
  Bottom 0.152: v353.69,59.05 353.69,60.32 330.2,83.82 330.2,88.27 331.47,89.54 318.13,102.87 318.13,103.51 317.5,104.14 317.5,107.32 318.77,108.59 310.51,116.84 310.51,119.38 311.79,120.65 310.51,121.92 307.98,121.92 306.7,123.19 C08.F2
DA7-1  (via drill 0.61)
  Top 0.152: v247.01,28.58 247.01,29.21 286.38,68.58 287.02,68.58 288.29,69.85 v288.29,73.66 | v307.98,111.76 306.07,113.67 306.07,116.84 C08.J2
  Route2 0.152: v288.29,73.66 288.29,75.57 295.27,82.55 301.62,82.55 304.8,85.73 304.8,88.27 307.98,91.44 307.98,93.34 306.07,95.25 v313.69,102.87
  Bottom 0.152: v247.01,28.58 247.01,27.94 252.09,22.86 255.27,22.86 D12.T2 | v313.69,102.87 315.6,104.78 308.61,111.76 v307.98,111.76
DA7-2  (via drill 0.61)
  Top 0.152: v204.47,12.7 247.65,55.88 247.65,59.05 246.38,60.32 254,67.95 259.08,67.95 274.95,83.82 275.59,83.82 299.72,107.95 300.36,107.95 302.26,109.86 305.44,109.86 306.07,110.49 C08.L2
  Bottom 0.152: v204.47,12.7 195.58,21.59 192.41,21.59 D17.T2
DA7-3  (via drill 0.61)
  Route2 0.152: v151.13,5.71 151.76,5.71 153.67,7.62 154.94,7.62 155.57,8.26 156.84,8.26 158.12,9.53 191.77,9.53 193.68,11.43 205.74,11.43 v207.01,12.7 | v244.47,1.91 284.48,41.91 284.48,42.55 287.65,45.72 288.29,45.72 290.83,48.26 292.1,48.26 292.74,48.89 297.18,48.89 299.08,50.8 299.72,50.8 319.4,70.48 319.4,71.75 v325.75,78.11
  Route15 0.152: v325.75,78.11 325.75,81.28 320.04,87 314.96,87 304.8,97.16 v304.8,98.43
  Bottom 0.152: v151.13,5.71 142.24,14.61 139.7,14.61 132.72,21.59 128.91,21.59 D22.T2 | v207.01,12.7 208.91,12.7 217.17,4.45 219.71,4.45 220.34,3.81 229.24,3.81 230.5,2.54 231.78,2.54 232.41,1.91 v244.47,1.91 | v304.8,98.43 304.8,100.97 307.34,103.51 306.7,104.14 C08.N2
DA7-4  (via drill 0.61)
  Top 0.152: v170.81,1.27 177.8,1.27 179.07,2.54 184.15,2.54 189.23,7.62 190.5,7.62 193.68,10.79 197.49,10.79 205.74,19.05 v206.38,19.05 | v269.24,57.78 269.24,58.42 280.04,69.22 280.04,73.66 290.83,84.46 290.83,86.36 297.81,93.34 298.45,93.34 302.26,97.16 305.44,97.16 306.07,97.79 C08.R2
  Route2 0.152: v112.39,1.91 113.67,1.91 116.84,5.08 123.19,5.08 124.46,6.35 130.81,6.35 132.08,7.62 142.24,7.62 v151.76,17.14 | v218.44,9.53 222.25,9.53 222.88,10.16 227.33,10.16 244.47,27.3 244.47,33.66 262.25,51.43 262.89,51.43 v269.24,57.78
  Bottom 0.152: v112.39,1.91 111.12,3.18 109.86,3.18 102.87,10.16 97.79,10.16 93.98,13.97 83.19,13.97 80.01,17.14 73.66,17.14 69.22,21.59 65.41,21.59 D27.T2 | v151.76,17.14 154.94,17.14 v170.81,1.27 | v206.38,19.05 206.38,17.78 210.19,13.97 214,13.97 v218.44,9.53
DA7-5  (via drill 0.61)
  Top 0.152: v280.67,77.47 276.86,77.47 v264.8,65.41 | v114.94,225.43 114.94,227.33 115.57,227.97 A23.T2
  Route2 0.152: v287.02,74.3 287.65,74.93 287.65,76.2 302.26,90.81 303.53,90.81 304.17,91.44 306.07,91.44 C08.T2
  Route15 0.152: v264.8,65.41 263.52,65.41 261.62,63.5 257.18,67.95 251.46,67.95 247.65,71.75 245.75,71.75 235.59,81.92 235.59,83.82 224.79,94.62 224.79,96.52 226.69,98.43 v203.84,121.29 | v193.68,137.16 193.68,137.8 191.77,139.7 191.77,142.88 164.47,170.18 163.83,170.18 162.56,171.45 162.56,172.72 135.89,199.39 135.89,201.3 137.79,203.2 135.89,205.11 134.62,205.11 133.35,206.38 133.35,207.01 v114.94,225.43
  Bottom 0.152: v287.02,74.3 283.85,74.3 v280.67,77.47 | v203.84,121.29 203.84,121.92 193.68,132.08 v193.68,137.16
DA7-6  (via drill 0.61)
  Top 0.152: v271.14,157.48 266.7,153.03 266.7,151.77 v262.25,147.32 | v313.06,96.52 313.69,95.89 310.51,92.71 310.51,90.17 311.79,88.9 310.51,87.63 309.25,87.63 306.7,85.09 C08.V2
  Route2 0.152: v140.97,285.11 136.53,280.67 124.46,280.67 123.83,280.03 121.92,280.03 120.02,278.13 111.76,278.13 105.41,271.78 98.42,271.78 55.88,229.24 52.7,229.24 A28.T2
  Route15 0.152: v221.62,212.09 225.43,212.09 v227.97,209.55
  Bottom 0.152: v140.97,285.11 145.41,285.11 210.19,220.34 213.36,220.34 v221.62,212.09 | v227.97,209.55 227.97,208.28 231.78,204.47 231.78,198.75 270.51,160.02 271.14,160.02 272.42,158.75 v271.14,157.48 | v262.25,147.32 273.05,147.32 282.57,137.8 282.57,131.44 314.96,99.06 314.96,97.16 313.69,95.89 v313.06,96.52
DA8  (via drill 0.61)
  Top 0.152: v247.65,225.43 247.65,224.16 231.78,208.28 231.78,207.65 217.81,193.68 217.81,191.14 B15.F2 | v281.31,205.74 281.31,210.19 285.75,214.63 287.65,214.63 288.29,215.27 290.83,215.27 298.45,222.89 298.45,223.52 299.08,224.16 301.62,224.16 303.53,222.25 v304.8,223.52
  Route15 0.152: v247.65,225.43 248.92,225.43 251.46,222.89 251.46,218.44 260.35,209.55 265.43,209.55 269.88,214 275.59,208.28 278.76,208.28 v281.31,205.74 | v304.8,223.52 308.61,223.52 311.79,220.34 314.32,220.34 316.23,222.25 317.5,220.98 318.13,220.98 318.77,221.62 A07.V2
DA8-0  (via drill 0.61)
  Top 0.152: v282.57,107.32 282.57,109.22 289.56,116.21 289.56,117.48 290.83,118.75 291.46,118.75 293.37,120.65 293.37,123.19 C09.F2
  Route2 0.152: v282.57,107.32 282.57,104.14 279.4,100.97 279.4,99.7 269.88,90.17 v269.88,89.54
  Route15 0.152: v269.88,89.54 269.88,87.63 270.51,87 270.51,85.73 285.75,70.48 285.75,69.85 287.02,68.58 288.29,68.58 v313.69,43.18
  Bottom 0.152: v313.69,43.18 318.13,38.73 318.13,37.47 309.25,28.58 318.13,19.69 318.13,17.14 318.77,16.51 D07.V2
DA8-1  (via drill 0.61)
  Top 0.152: v254,20.95 252.73,22.23 258.44,27.94 258.44,28.58 302.26,72.39 302.89,72.39 v306.07,75.57 | v280.67,100.97 280.67,101.6 292.74,113.67 292.74,116.21 293.37,116.84 C09.J2
  Bottom 0.152: v254,20.95 255.27,19.69 255.27,16.51 D12.V2 | v306.07,75.57 306.07,76.2 291.46,90.81 290.83,90.81 288.93,92.71 288.93,93.34 286.38,95.89 285.75,95.89 v280.67,100.97
DA8-2  (via drill 0.61)
  Top 0.152: v267.97,93.98 267.33,93.98 252.09,78.74 252.09,77.47 246.38,71.75 245.11,71.75 233.68,60.32 234.95,59.05 234.95,55.88 209.55,30.48 208.28,30.48 206.38,28.58 206.38,27.3 195.58,16.51 192.41,16.51 D17.V2 | v273.05,88.9 273.05,90.81 271.78,92.08 276.86,97.16 282.57,97.16 292.74,107.32 292.74,109.86 293.37,110.49 C09.L2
